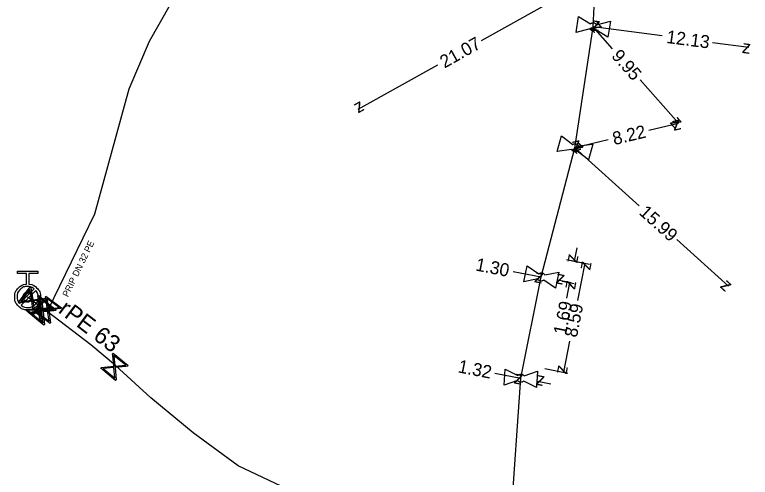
# Model space of a CAD drawing. Extents: x -638315 to -636370, y -1116147 to -1115110.
# Drawn here: x -637132.7 to -637075.7, y -1115952.2 to -1115916.4 of the extents above; entities that cross this region are included whole.
import ezdxf

# ---------------------------------------------------------------- set-up
doc = ezdxf.new("R2010")
doc.units = 0
for name, color, linetype in [('Default', 7, 'Continuous'), ('VP Hydrant', 7, 'Continuous'), ('VP Kótování', 7, 'Continuous'), ('VP Lomový bod', 7, 'Continuous'), ('VP Popis přípojky', 7, 'Continuous'), ('VP Přípojka', 7, 'Continuous'), ('VP Řad', 7, 'Continuous'), ('VP Řad - popis', 7, 'Continuous'), ('VP Šoupě', 7, 'Continuous')]:
    doc.layers.add(name, color=color, linetype=linetype)

msp = doc.modelspace()

# ---------------------------------------------------------------- linework, layer by layer
at = {"layer": 'Default'}
for points in [[(-637088.094, -1115917.128), (-637088.054, -1115917.095), (-637088.004, -1115917.075), (-637087.923, -1115917.046), (-637087.842, -1115917.058), (-637087.761, -1115917.07), (-637087.695, -1115917.122), (-637087.652, -1115917.156), (-637087.624, -1115917.201)], [(-637087.686, -1115917.604), (-637087.726, -1115917.639), (-637087.777, -1115917.658), (-637087.856, -1115917.688), (-637087.936, -1115917.676), (-637088.017, -1115917.663), (-637088.086, -1115917.61), (-637088.128, -1115917.578), (-637088.155, -1115917.533)], [(-637089.479, -1115926.461), (-637089.436, -1115926.432), (-637089.384, -1115926.418), (-637089.301, -1115926.397), (-637089.221, -1115926.417), (-637089.142, -1115926.438), (-637089.082, -1115926.497), (-637089.043, -1115926.535), (-637089.02, -1115926.582)], [(-637089.123, -1115926.977), (-637089.166, -1115927.007), (-637089.219, -1115927.021), (-637089.3, -1115927.043), (-637089.379, -1115927.022), (-637089.459, -1115927.001), (-637089.521, -1115926.941), (-637089.559, -1115926.904), (-637089.582, -1115926.857)], [(-637092.103, -1115936.462), (-637092.062, -1115936.431), (-637092.011, -1115936.414), (-637091.928, -1115936.388), (-637091.848, -1115936.404), (-637091.768, -1115936.42), (-637091.704, -1115936.475), (-637091.663, -1115936.511), (-637091.638, -1115936.557)], [(-637091.718, -1115936.957), (-637091.76, -1115936.99), (-637091.812, -1115937.007), (-637091.892, -1115937.033), (-637091.972, -1115937.017), (-637092.052, -1115937.001), (-637092.118, -1115936.944), (-637092.158, -1115936.909), (-637092.184, -1115936.863)], [(-637131.556, -1115937.264), (-637131.196, -1115937.294), (-637130.939, -1115937.555), (-637130.649, -1115937.848), (-637130.65, -1115938.264), (-637130.651, -1115938.678), (-637130.945, -1115938.97), (-637131.239, -1115939.261), (-637131.655, -1115939.26), (-637132.067, -1115939.259), (-637132.359, -1115938.966), (-637132.651, -1115938.673), (-637132.65, -1115938.259), (-637132.649, -1115937.843), (-637132.357, -1115937.551), (-637132.099, -1115937.29), (-637131.739, -1115937.264)], [(-637131.141, -1115937.624), (-637131.357, -1115937.446), (-637131.65, -1115937.445), (-637131.988, -1115937.445), (-637132.226, -1115937.681), (-637132.464, -1115937.918), (-637132.465, -1115938.256), (-637132.465, -1115938.549), (-637132.288, -1115938.766)], [(-637132.16, -1115938.895), (-637131.943, -1115939.07), (-637131.654, -1115939.07), (-637131.318, -1115939.071), (-637131.079, -1115938.835), (-637130.84, -1115938.598), (-637130.84, -1115938.26), (-637130.839, -1115937.971), (-637131.012, -1115937.754)], [(-637131.65, -1115937.885), (-637131.556, -1115937.885), (-637131.466, -1115937.933), (-637131.376, -1115937.982), (-637131.326, -1115938.072), (-637131.275, -1115938.162), (-637131.275, -1115938.26), (-637131.275, -1115938.358), (-637131.324, -1115938.447), (-637131.374, -1115938.536), (-637131.463, -1115938.586), (-637131.553, -1115938.635), (-637131.65, -1115938.635), (-637131.747, -1115938.635), (-637131.837, -1115938.586), (-637131.926, -1115938.536), (-637131.976, -1115938.447), (-637132.025, -1115938.358), (-637132.025, -1115938.26), (-637132.025, -1115938.162), (-637131.975, -1115938.072), (-637131.924, -1115937.982), (-637131.835, -1115937.933), (-637131.745, -1115937.885), (-637131.65, -1115937.885)], [(-637131.65, -1115937.932), (-637131.733, -1115937.932), (-637131.812, -1115937.974), (-637131.89, -1115938.016), (-637131.934, -1115938.095), (-637131.978, -1115938.174), (-637131.978, -1115938.26), (-637131.978, -1115938.346), (-637131.935, -1115938.424), (-637131.892, -1115938.501), (-637131.814, -1115938.545), (-637131.735, -1115938.588), (-637131.65, -1115938.588), (-637131.565, -1115938.588), (-637131.486, -1115938.545), (-637131.408, -1115938.501), (-637131.365, -1115938.424), (-637131.322, -1115938.346), (-637131.322, -1115938.26), (-637131.322, -1115938.174), (-637131.366, -1115938.095), (-637131.411, -1115938.016), (-637131.489, -1115937.974), (-637131.568, -1115937.932), (-637131.65, -1115937.932)], [(-637093.713, -1115944.319), (-637093.677, -1115944.282), (-637093.628, -1115944.259), (-637093.55, -1115944.223), (-637093.468, -1115944.228), (-637093.387, -1115944.234), (-637093.317, -1115944.28), (-637093.271, -1115944.31), (-637093.24, -1115944.353)], [(-637093.268, -1115944.76), (-637093.305, -1115944.797), (-637093.354, -1115944.821), (-637093.43, -1115944.857), (-637093.511, -1115944.852), (-637093.593, -1115944.846), (-637093.666, -1115944.798), (-637093.71, -1115944.769), (-637093.741, -1115944.727)]]:
    msp.add_open_spline(points, degree=3, dxfattribs=at)
at = {"layer": 'VP Hydrant'}
for points in [[(-637131.739, -1115937.264), (-637131.737, -1115936.443), (-637132.427, -1115936.441), (-637132.426, -1115936.258), (-637130.864, -1115936.262), (-637130.864, -1115936.445), (-637131.554, -1115936.444), (-637131.556, -1115937.264)], [(-637132.288, -1115938.766), (-637131.141, -1115937.624)], [(-637131.012, -1115937.754), (-637132.16, -1115938.895)]]:
    msp.add_lwpolyline(points, dxfattribs=at)
at = {"layer": 'VP Kótování'}
for points in [[(-637096.537, -1115918.423), (-637087.7, -1115913.477)], [(-637086.39, -1115919.062), (-637087.889, -1115917.367)], [(-637082.548, -1115918.07), (-637087.889, -1115917.367)], [(-637078.673, -1115918.58), (-637075.86, -1115918.95)], [(-637099.948, -1115920.332), (-637106.09, -1115923.77)], [(-637084.264, -1115921.467), (-637081.3, -1115924.82)], [(-637083.6, -1115925.366), (-637081.3, -1115924.82)], [(-637086.722, -1115926.108), (-637089.3, -1115926.72)], [(-637084.331, -1115931.204), (-637089.3, -1115926.72)], [(-637081.429, -1115933.822), (-637077.43, -1115937.43)], [(-637089.168, -1115934.456), (-637089.372, -1115935.486)], [(-637089.967, -1115935.368), (-637088.178, -1115935.722)], [(-637089.967, -1115935.368), (-637089.029, -1115935.554)], [(-637089.092, -1115938.535), (-637088.522, -1115935.654)], [(-637094.092, -1115936.277), (-637091.91, -1115936.71)], [(-637089.609, -1115937.166), (-637090.639, -1115936.962)], [(-637090.296, -1115937.03), (-637089.358, -1115937.216)], [(-637089.938, -1115938.344), (-637089.701, -1115937.148)], [(-637089.716, -1115941.682), (-637090.192, -1115944.084)], [(-637091.637, -1115943.798), (-637089.848, -1115944.152)], [(-637095.507, -1115944.141), (-637093.49, -1115944.54)], [(-637091.161, -1115945.001), (-637092.191, -1115944.797)]]:
    msp.add_lwpolyline(points, dxfattribs=at)
at = {"layer": 'VP Lomový bod'}
for points in [[(-637089.219, -1115917.796), (-637089.031, -1115916.561), (-637088.094, -1115917.128)], [(-637087.624, -1115917.201), (-637086.559, -1115916.937), (-637086.748, -1115918.173), (-637087.686, -1115917.604)], [(-637088.155, -1115917.533), (-637089.219, -1115917.796)], [(-637090.668, -1115927.008), (-637090.352, -1115925.799), (-637089.479, -1115926.461)], [(-637089.02, -1115926.582), (-637087.933, -1115926.431), (-637088.249, -1115927.64), (-637089.123, -1115926.977)], [(-637089.582, -1115926.857), (-637090.668, -1115927.008)], [(-637093.259, -1115937.076), (-637093.012, -1115935.851), (-637092.103, -1115936.462)], [(-637091.638, -1115936.557), (-637090.561, -1115936.345), (-637090.808, -1115937.57), (-637091.718, -1115936.957)], [(-637092.184, -1115936.863), (-637093.259, -1115937.076)], [(-637094.78, -1115945.077), (-637094.694, -1115943.83), (-637093.713, -1115944.319)], [(-637093.24, -1115944.353), (-637092.2, -1115944.002), (-637092.286, -1115945.249), (-637093.268, -1115944.76)], [(-637093.741, -1115944.727), (-637094.78, -1115945.077)]]:
    msp.add_lwpolyline(points, dxfattribs=at)
at = {"layer": 'VP Přípojka'}
for points in [[(-637130.14, -1115939.39), (-637130.073, -1115939.252), (-637126.46, -1115931.82), (-637123.79, -1115922.17), (-637122.22, -1115918.47), (-637120.62, -1115915.67), (-637119.74, -1115914.32), (-637118.52, -1115913.31)], [(-637087.889, -1115917.367), (-637087.69, -1115917.39)], [(-637130.728, -1115939.184), (-637130.63, -1115939.07)], [(-637130.508, -1115939.374), (-637130.41, -1115939.26)], [(-637124.94, -1115943.66), (-637124.84, -1115943.56)]]:
    msp.add_lwpolyline(points, dxfattribs=at)
at = {"layer": 'VP Řad'}
for points in [[(-637094.23, -1115955.262), (-637093.49, -1115944.54), (-637091.91, -1115936.71), (-637089.3, -1115926.72), (-637089.319, -1115926.747), (-637087.994, -1115918.056), (-637087.889, -1115917.367), (-637087.796, -1115915.284), (-637087.73, -1115913.837), (-637087.7, -1115913.477), (-637088.089, -1115910.373), (-637089.63, -1115905.6), (-637092.67, -1115900.43), (-637096.292, -1115895.507), (-637097.135, -1115894.376), (-637097.592, -1115893.907), (-637098.02, -1115893.26), (-637101.99, -1115889.44), (-637106.08, -1115883.61), (-637108.074, -1115879.731), (-637111.304, -1115873.45)], [(-637094.23, -1115955.262), (-637101.32, -1115955.03), (-637105.251, -1115954.422), (-637106.04, -1115954.3), (-637111.55, -1115953.13), (-637115.37, -1115951.32), (-637118.85, -1115948.77), (-637122.11, -1115946.05), (-637124.84, -1115943.56), (-637126.75, -1115941.96), (-637130.14, -1115939.39), (-637130.41, -1115939.26), (-637130.63, -1115939.07), (-637131.29, -1115938.52), (-637131.65, -1115938.26)]]:
    msp.add_lwpolyline(points, dxfattribs=at)
at = {"layer": 'VP Šoupě'}
for points in [[(-637130.249, -1115938.383), (-637131.148, -1115939.584), (-637131.201, -1115939.544), (-637131.215, -1115939.417), (-637131.336, -1115938.585), (-637132.296, -1115938.724), (-637132.349, -1115938.685), (-637131.45, -1115937.484), (-637131.397, -1115937.524), (-637131.261, -1115938.486), (-637130.43, -1115938.365), (-637130.302, -1115938.343), (-637130.249, -1115938.383)], [(-637132.183, -1115938.619), (-637131.348, -1115938.498), (-637131.469, -1115937.666), (-637132.183, -1115938.619)], [(-637130.809, -1115938.126), (-637129.67, -1115939.103), (-637129.713, -1115939.153), (-637129.842, -1115939.158), (-637130.679, -1115939.224), (-637130.604, -1115940.191), (-637130.647, -1115940.242), (-637131.786, -1115939.265), (-637131.743, -1115939.215), (-637130.774, -1115939.143), (-637130.839, -1115938.305), (-637130.852, -1115938.177), (-637130.809, -1115938.126)], [(-637130.626, -1115938.32), (-637129.454, -1115939.256), (-637129.495, -1115939.308), (-637129.623, -1115939.318), (-637130.458, -1115939.412), (-637130.349, -1115940.377), (-637130.39, -1115940.428), (-637131.562, -1115939.492), (-637131.521, -1115939.44), (-637130.555, -1115939.334), (-637130.649, -1115938.5), (-637130.667, -1115938.371), (-637130.626, -1115938.32)], [(-637130.419, -1115938.453), (-637131.249, -1115938.573), (-637131.128, -1115939.401), (-637130.419, -1115938.453)], [(-637130.236, -1115938.204), (-637129.025, -1115939.089), (-637129.064, -1115939.142), (-637129.191, -1115939.158), (-637130.021, -1115939.288), (-637129.87, -1115940.247), (-637129.909, -1115940.3), (-637131.121, -1115939.415), (-637131.082, -1115939.362), (-637130.121, -1115939.215), (-637130.252, -1115938.385), (-637130.275, -1115938.257), (-637130.236, -1115938.204)], [(-637130.751, -1115938.3), (-637130.686, -1115939.136), (-637129.852, -1115939.071), (-637130.751, -1115938.3)], [(-637130.561, -1115938.491), (-637130.468, -1115939.325), (-637129.636, -1115939.231), (-637130.561, -1115938.491)], [(-637130.164, -1115938.373), (-637130.034, -1115939.201), (-637129.208, -1115939.071), (-637130.164, -1115938.373)], [(-637130.701, -1115940.071), (-637130.767, -1115939.231), (-637131.606, -1115939.296), (-637130.701, -1115940.071)], [(-637129.977, -1115940.135), (-637130.108, -1115939.302), (-637130.939, -1115939.432), (-637129.977, -1115940.135)], [(-637130.451, -1115940.26), (-637130.545, -1115939.422), (-637131.381, -1115939.516), (-637130.451, -1115940.26)], [(-637125.033, -1115942.603), (-637123.883, -1115943.567), (-637123.925, -1115943.617), (-637124.054, -1115943.624), (-637124.89, -1115943.699), (-637124.804, -1115944.666), (-637124.846, -1115944.716), (-637125.996, -1115943.753), (-637125.954, -1115943.703), (-637124.986, -1115943.619), (-637125.061, -1115942.783), (-637125.075, -1115942.654), (-637125.033, -1115942.603)], [(-637124.972, -1115942.776), (-637124.898, -1115943.612), (-637124.065, -1115943.537), (-637124.972, -1115942.776)], [(-637124.903, -1115944.547), (-637124.978, -1115943.707), (-637125.816, -1115943.782), (-637124.903, -1115944.547)]]:
    msp.add_lwpolyline(points, dxfattribs=at)

# ---------------------------------------------------------------- texts
at = {"layer": 'VP Kótování'}
for s, rotation, p in [('z', 131.479, (-637087.183, -1115917.41)), ('z', 172.503, (-637087.328, -1115916.937)), ('12.13', 352.5031, (-637082.266, -1115918.611)), ('21.07', 29.236, (-637099.398, -1115920.597)), ('z', 352.503, (-637076.421, -1115919.38)), ('9.95', 311.4791, (-637086.533, -1115919.656)), ('z', 209.236, (-637105.898, -1115923.089)), ('z', 311.4791, (-637082.006, -1115924.777)), ('8.22', 13.3602, (-637086.266, -1115926.513)), ('z', 13.3602, (-637081.671, -1115925.422)), ('z', 193.3602, (-637088.929, -1115926.118)), ('z', 137.9408, (-637088.594, -1115926.684)), ('15.99', 317.9409, (-637084.406, -1115931.809)), ('1.30', 348.7855, (-637097.047, -1115936.201)), ('z', 258.8028, (-637089.766, -1115934.898)), ('z', 78.7946, (-637088.128, -1115936.242)), ('z', 348.7854, (-637092.498, -1115937.103)), ('z', 168.7855, (-637090.051, -1115936.569)), ('z', 78.8028, (-637089.308, -1115937.735)), ('z', 317.9409, (-637078.136, -1115937.466)), ('1.69', 78.8028, (-637090.003, -1115941.245)), ('8.59', 78.7946, (-637089.157, -1115941.436)), ('1.32', 348.8089, (-637098.408, -1115944.077)), ('z', 258.7947, (-637090.585, -1115943.497)), ('z', 348.8089, (-637094.078, -1115944.933)), ('z', 168.8089, (-637091.603, -1115944.404))]:
    msp.add_text(s, height=1, rotation=rotation, dxfattribs=at).set_placement(p)
at = {"layer": 'VP Popis přípojky'}
msp.add_text('PRIP DN 32 PE', height=0.5, rotation=64.0762, dxfattribs=at).set_placement((-637128.535, -1115938.301))
at = {"layer": 'VP Řad - popis'}
msp.add_text('rPE 63', height=1.3, rotation=322.8338, dxfattribs=at).set_placement((-637129.348, -1115939.417))

doc.saveas('drawing.dxf')
